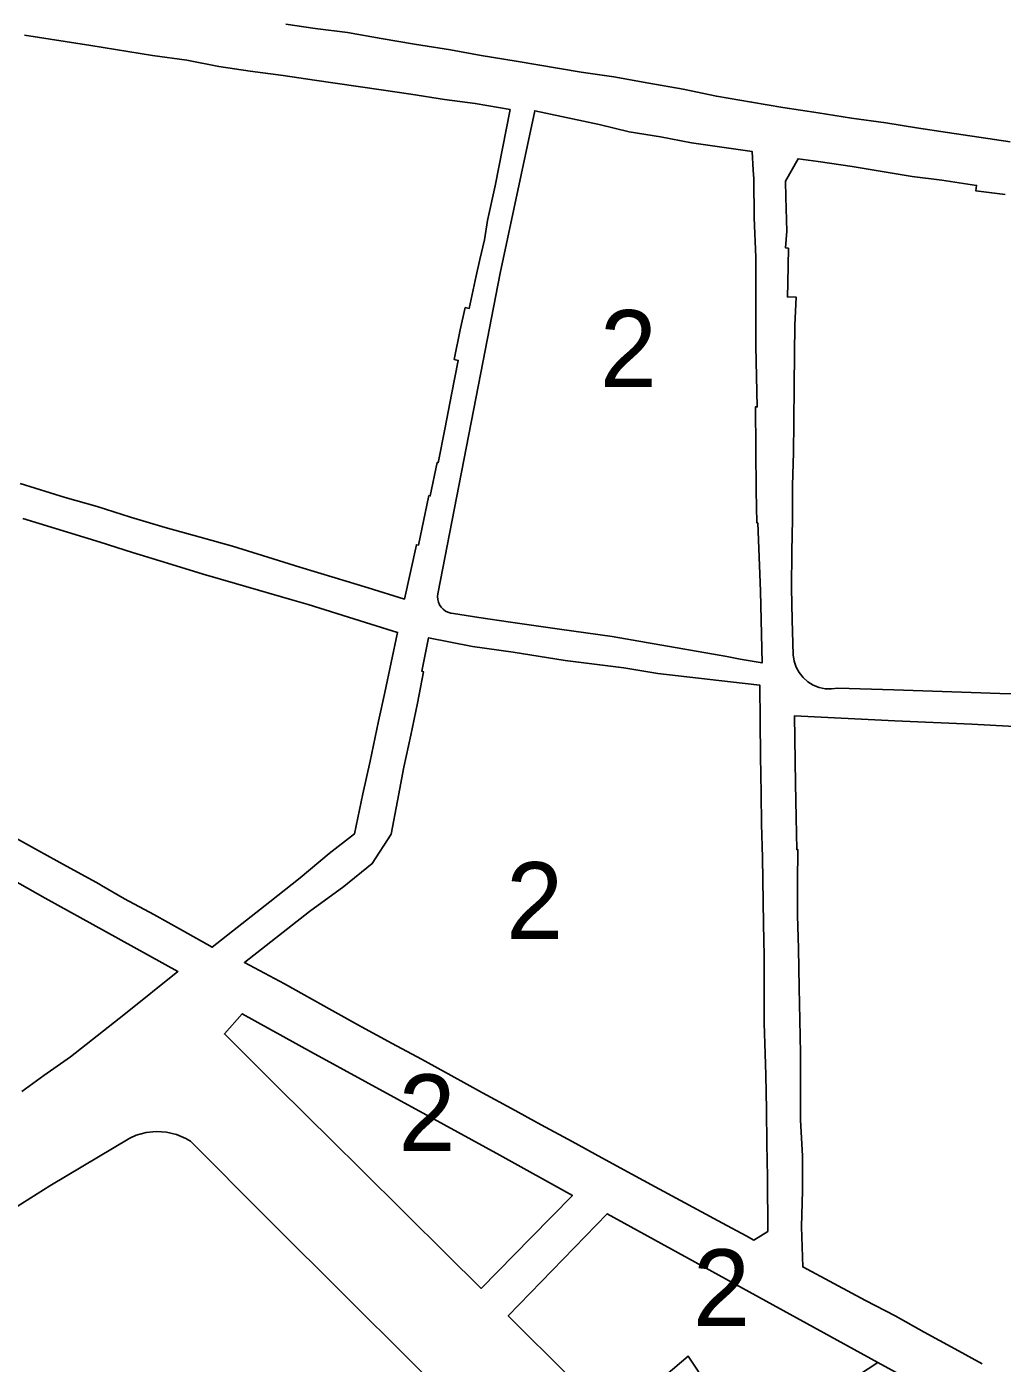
# Model space of a CAD drawing. Extents: x 598968 to 613553, y 4409678 to 4430833.
# Drawn here: x 607715.2 to 607867.8, y 4416080 to 4416289 of the extents above; entities that cross this region are included whole.
import ezdxf

# ---------------------------------------------------------------- set-up
doc = ezdxf.new("R2010")
doc.units = 0
for name, color, linetype in [('1', 7, 'Continuous'), ('SUBZONA 2e. CARRERS DE CASES. amb projecte especial', 7, 'Continuous'), ('ZONA 2. CARRERS DE CASES. Cases de trast', 7, 'Continuous')]:
    doc.layers.add(name, color=color, linetype=linetype)

msp = doc.modelspace()

# ---------------------------------------------------------------- linework, layer by layer
at = {"layer": '1'}
for points in [[(607714.8669, 4416287.693), (607725.2068, 4416286.0432), (607734.8867, 4416284.4934), (607740.2266, 4416283.7635), (607745.2466, 4416282.7836), (607750.1465, 4416282.0336), (607755.2965, 4416281.3537), (607760.1964, 4416280.6438), (607770.6563, 4416279.114), (607775.2663, 4416278.4641), (607780.5362, 4416277.6342), (607785.3561, 4416276.9943), (607790.7961, 4416276.0444), (607788.4661, 4416264.1145), (607787.2962, 4416258.7046), (607786.7862, 4416255.6646), (607786.0962, 4416252.5846), (607785.5205, 4416250.0336), (607784.4063, 4416244.9547), (607783.7863, 4416245.0847), (607783.0063, 4416241.5947), (607782.0763, 4416236.9447), (607782.7063, 4416236.8148), (607781.6473, 4416231.4626), (607780.6464, 4416226.3048), (607779.5464, 4416220.8249), (607779.4164, 4416220.8549), (607778.3186, 4416215.6402), (607778.1064, 4416215.6849), (607776.4765, 4416207.935), (607776.1665, 4416207.995), (607774.2765, 4416199.4851), (607768.5866, 4416201.2349), (607763.4356, 4416202.8436), (607757.9167, 4416204.5047), (607755.4167, 4416205.2746), (607752.9168, 4416206.0446), (607747.3982, 4416207.7807), (607742.3469, 4416209.1644), (607736.8669, 4416210.7143), (607731.4103, 4416212.3258), (607726.197, 4416213.984), (607721.2371, 4416215.4039), (607714.1772, 4416217.5738)], [(607869.0152, 4416270.9859), (607859.2305, 4416272.4599), (607854.3954, 4416273.1656), (607849.5937, 4416273.9605), (607844.1855, 4416274.6854), (607838.9965, 4416275.5066), (607833.4656, 4416276.3852), (607828.5707, 4416277.2173), (607823.0857, 4416278.125), (607817.8758, 4416279.2249), (607812.4858, 4416280.1848), (607807.0359, 4416281.1547), (607801.9459, 4416281.8846), (607791.756, 4416283.6044), (607786.3061, 4416284.4843), (607781.4662, 4416285.3742), (607775.8562, 4416286.284), (607770.6463, 4416287.1439), (607765.3963, 4416288.0738), (607760.3364, 4416288.6937), (607755.7264, 4416289.3937)], [(607871.1255, 4416184.6369), (607867.3855, 4416184.7569), (607862.9156, 4416184.8968), (607850.8107, 4416185.2816), (607842.0558, 4416185.5764), (607841.0791, 4416185.4468), (607840.0947, 4416185.4861), (607839.1314, 4416185.693), (607838.2177, 4416186.0614), (607837.3804, 4416186.5807), (607836.6441, 4416187.2354), (607836.0307, 4416188.0063), (607835.558, 4416188.8707), (607835.2399, 4416189.8031), (607835.0859, 4416190.7762), (607834.9258, 4416196.2262), (607834.8358, 4416201.2061), (607834.8558, 4416206.956), (607834.9658, 4416211.986), (607834.9758, 4416217.2359), (607835.1157, 4416222.4359), (607835.1657, 4416227.0958), (607835.2257, 4416232.8357), (607835.2757, 4416237.7757), (607835.3257, 4416242.3456), (607835.5657, 4416246.7056), (607834.1857, 4416246.7444), (607834.2457, 4416248.8755), (607834.3456, 4416254.3655), (607833.8957, 4416254.3954), (607834.0756, 4416257.0254), (607833.9456, 4416262.3654), (607833.8756, 4416264.8353), (607835.8556, 4416268.3553), (607838.9955, 4416267.9054), (607844.2955, 4416267.1355), (607853.7054, 4416265.5857), (607858.3153, 4416264.9958), (607863.7753, 4416264.1759), (607863.6668, 4416263.3157), (607868.2652, 4416262.736)], [(607714.5844, 4416212.0789), (607726.6937, 4416208.4216), (607731.737, 4416206.7942), (607737.1969, 4416205.1243), (607742.8169, 4416203.3944), (607747.8768, 4416201.9446), (607756.6767, 4416199.3747), (607759.2367, 4416198.6448), (607768.1666, 4416195.855), (607773.2166, 4416194.2751), (607772.2066, 4416189.5701), (607771.1966, 4416184.8652), (607770.2466, 4416180.4252), (607768.8967, 4416174.1353), (607767.7967, 4416169.0453), (607766.4567, 4416162.7753), (607762.4868, 4416159.7353), (607757.9669, 4416155.8953), (607753.2369, 4416152.1552), (607748.097, 4416148.1252), (607744.1871, 4416145.0652), (607739.5871, 4416147.6651), (607735.0872, 4416150.1549), (607730.4972, 4416152.6148), (607726.9201, 4416154.6959), (607726.7214, 4416154.8115), (607726.0972, 4416155.1747), (607721.4073, 4416157.7246), (607716.9073, 4416160.2145), (607712.1974, 4416162.8244)], [(607864.6559, 4416079.9281), (607860.3559, 4416082.268), (607855.576, 4416084.8578), (607851.0145, 4416087.4439), (607846.4195, 4416089.8418), (607841.4361, 4416092.4775), (607836.5762, 4416095.0774), (607836.4061, 4416101.3273), (607836.5561, 4416106.9972), (607836.5261, 4416112.4572), (607836.2161, 4416118.0171), (607836.2061, 4416123.217), (607836.2061, 4416128.497), (607836.126, 4416133.7169), (607836.036, 4416138.7069), (607835.896, 4416144.8768), (607835.776, 4416150.0267), (607835.776, 4416155.1767), (607835.826, 4416160.3166), (607835.636, 4416160.3366), (607835.5559, 4416165.3265), (607835.4554, 4416170.6461), (607835.2759, 4416181.2263), (607851.0057, 4416180.4766), (607863.0156, 4416179.9368), (607878.2854, 4416179.1171)], [(607708.522, 4416158.0906), (607718.0973, 4416152.7546), (607727.5472, 4416147.5148), (607738.8571, 4416141.2851), (607730.6773, 4416134.705), (607726.2273, 4416131.195), (607722.0674, 4416127.945), (607717.8874, 4416124.9849), (607714.4175, 4416122.5149)], [(607698.8973, 4416095.1959), (607716.8354, 4416106.5031), (607718.8375, 4416107.7652), (607731.3173, 4416115.1753), (607732.3273, 4416115.6453), (607733.8773, 4416116.0653), (607735.4673, 4416116.2254), (607736.2673, 4416116.2054), (607737.0672, 4416116.1254), (607738.6272, 4416115.7554), (607740.0972, 4416115.1354), (607740.7972, 4416114.7455), (607752.5934, 4416102.8813), (607765.7365, 4416089.816), (607774.5369, 4416081.0865), (607806.3427, 4416049.5958)], [(607806.3427, 4416049.5958), (607774.5369, 4416081.0865), (607765.7365, 4416089.816), (607752.5934, 4416102.8813), (607740.7972, 4416114.7455), (607740.0972, 4416115.1354), (607738.6272, 4416115.7554), (607737.0672, 4416116.1254), (607736.2673, 4416116.2054), (607735.4673, 4416116.2254), (607733.8773, 4416116.0653), (607732.3273, 4416115.6453), (607731.3173, 4416115.1753), (607718.8375, 4416107.7652), (607716.8354, 4416106.5031), (607698.8973, 4416095.1959)]]:
    msp.add_lwpolyline(points, dxfattribs=at)
for points in [[(607789.2462, 4416250.4547), (607794.676, 4416275.8445), (607804.7459, 4416273.6947), (607809.4259, 4416272.5748), (607814.322, 4416271.7676), (607819.1858, 4416270.845), (607828.6757, 4416269.4652), (607828.8457, 4416266.5552), (607828.9257, 4416265.2152), (607828.9957, 4416259.1153), (607829.2557, 4416252.9454), (607829.2434, 4416239.0518), (607829.4658, 4416229.5357), (607829.1858, 4416229.5557), (607829.2958, 4416216.4258), (607829.3959, 4416211.4259), (607829.5459, 4416211.4059), (607829.9759, 4416200.756), (607830.2259, 4416189.5162), (607826.786, 4416190.1261), (607824.696, 4416190.496), (607812.1261, 4416192.6958), (607806.7662, 4416193.6357), (607798.5363, 4416194.8055), (607790.8464, 4416195.9054), (607785.9064, 4416196.6153), (607781.9664, 4416197.2452), (607781.5222, 4416197.3002), (607781.094, 4416197.4306), (607780.6946, 4416197.6326), (607780.3357, 4416197.9002), (607780.0281, 4416198.2254), (607779.7808, 4416198.5985), (607779.6013, 4416199.0086), (607779.4949, 4416199.4433), (607779.4646, 4416199.8899), (607779.5115, 4416200.3351), (607783.1864, 4416219.325), (607786.2163, 4416234.8948)], [(607784.9486, 4416192.1054), (607791.2964, 4416191.1954), (607799.4092, 4416189.9064), (607808.5962, 4416188.7352), (607813.9276, 4416187.8547), (607825.296, 4416186.5561), (607829.8759, 4416186.0162), (607829.926, 4416180.3913), (607829.976, 4416174.9117), (607830.086, 4416169.0764), (607830.136, 4416164.3165), (607830.266, 4416159.0865), (607830.4461, 4416148.7366), (607830.5561, 4416143.6467), (607830.5461, 4416133.1968), (607830.6861, 4416128.3869), (607830.8161, 4416125.09), (607830.8961, 4416119.617), (607830.9462, 4416114.3071), (607831.0762, 4416109.0771), (607831.1262, 4416100.6172), (607828.9362, 4416099.2672), (607827.7362, 4416099.9172), (607824.0563, 4416101.9071), (607813.5164, 4416107.6068), (607809.8564, 4416109.5867), (607805.1638, 4416112.1301), (607800.5065, 4416114.6965), (607795.6746, 4416117.3096), (607791.0166, 4416119.8263), (607786.4967, 4416122.2862), (607781.6067, 4416124.9761), (607776.9267, 4416127.5459), (607772.3568, 4416129.9958), (607767.5468, 4416132.6357), (607762.9669, 4416135.1556), (607755.5338, 4416139.3228), (607749.247, 4416142.6753), (607759.4569, 4416150.6354), (607764.7868, 4416154.5754), (607769.2467, 4416158.1255), (607772.2167, 4416162.7454), (607773.1767, 4416167.9554), (607774.1766, 4416173.2154), (607775.2566, 4416178.1953), (607776.3166, 4416183.2153), (607777.2565, 4416188.1452), (607777.0165, 4416188.2152), (607778.0465, 4416193.4452)], [(607759.7469, 4416128.6356), (607768.1369, 4416124.0508), (607778.2668, 4416118.5211), (607789.1767, 4416112.5663), (607800.5665, 4416106.2466), (607794.0966, 4416099.6566), (607786.3068, 4416091.6965), (607780.7568, 4416097.1864), (607774.5719, 4416103.3212), (607767.188, 4416110.6176), (607763.1969, 4416114.5659), (607754.357, 4416123.3056), (607746.1271, 4416131.5054), (607748.917, 4416134.6454)], [(607866.7359, 4416070.1182), (607867.1096, 4416066.4683), (607838.2363, 4416047.598), (607836.0751, 4416046.2713), (607835.1768, 4416046.0285), (607834.2515, 4416045.9313), (607833.3224, 4416045.9819), (607832.413, 4416046.1791), (607831.5464, 4416046.5179), (607824.5964, 4416053.4577), (607809.7886, 4416068.2553), (607809.7833, 4416068.2513), (607790.5067, 4416087.4167), (607805.9765, 4416103.3868), (607848.3261, 4416080.1378), (607856.156, 4416075.858)]]:
    msp.add_lwpolyline(points, close=True, dxfattribs=at)
at = {"layer": 'SUBZONA 2e. CARRERS DE CASES. amb projecte especial'}
for points in [[(607821.7464, 4416076.4873), (607818.6564, 4416081.1272), (607815.1757, 4416078.1314)], [(607856.156, 4416075.858), (607848.3261, 4416080.1378), (607835.1774, 4416071.5183)]]:
    msp.add_lwpolyline(points, dxfattribs=at)
at = {"layer": 'ZONA 2. CARRERS DE CASES. Cases de trast'}
for points in [[(607714.1772, 4416217.5738), (607721.2371, 4416215.4039), (607726.197, 4416213.984), (607731.4103, 4416212.3258), (607736.8669, 4416210.7143), (607742.3469, 4416209.1644), (607747.3982, 4416207.7807), (607752.9168, 4416206.0446), (607755.4167, 4416205.2746), (607757.9167, 4416204.5047), (607763.4356, 4416202.8436), (607768.5866, 4416201.2349), (607774.2765, 4416199.4851), (607776.1665, 4416207.995), (607776.4765, 4416207.935), (607778.1064, 4416215.6849), (607778.3186, 4416215.6402), (607779.4164, 4416220.8549), (607779.5464, 4416220.8249), (607780.6464, 4416226.3048), (607781.6473, 4416231.4626), (607782.7063, 4416236.8148), (607782.0763, 4416236.9447), (607783.0063, 4416241.5947), (607783.7863, 4416245.0847), (607784.4063, 4416244.9547), (607785.5205, 4416250.0336), (607786.0962, 4416252.5846), (607786.7862, 4416255.6646), (607787.2962, 4416258.7046), (607788.4661, 4416264.1145), (607790.7961, 4416276.0444), (607785.3561, 4416276.9943), (607780.5362, 4416277.6342), (607775.2663, 4416278.4641), (607770.6563, 4416279.114), (607760.1964, 4416280.6438), (607755.2965, 4416281.3537), (607750.1465, 4416282.0336), (607745.2466, 4416282.7836), (607740.2266, 4416283.7635), (607734.8867, 4416284.4934), (607725.2068, 4416286.0432), (607714.8669, 4416287.693)], [(607755.7264, 4416289.3937), (607760.3364, 4416288.6937), (607765.3963, 4416288.0738), (607770.6463, 4416287.1439), (607775.8562, 4416286.284), (607781.4662, 4416285.3742), (607786.3061, 4416284.4843), (607791.756, 4416283.6044), (607801.9459, 4416281.8846), (607807.0359, 4416281.1547), (607812.4858, 4416280.1848), (607817.8758, 4416279.2249), (607823.0857, 4416278.125), (607828.5707, 4416277.2173), (607833.4656, 4416276.3852), (607838.9965, 4416275.5066), (607844.1855, 4416274.6854), (607849.5937, 4416273.9605), (607854.3954, 4416273.1656), (607859.2305, 4416272.4599), (607869.0152, 4416270.9859)], [(607868.2652, 4416262.736), (607863.6668, 4416263.3157), (607863.7753, 4416264.1759), (607858.3153, 4416264.9958), (607853.7054, 4416265.5857), (607844.2955, 4416267.1355), (607838.9955, 4416267.9054), (607835.8556, 4416268.3553), (607833.8756, 4416264.8353), (607833.9456, 4416262.3654), (607834.0756, 4416257.0254), (607833.8957, 4416254.3954), (607834.3456, 4416254.3655), (607834.2457, 4416248.8755), (607834.1857, 4416246.7444), (607835.5657, 4416246.7056), (607835.3257, 4416242.3456), (607835.2757, 4416237.7757), (607835.2257, 4416232.8357), (607835.1657, 4416227.0958), (607835.1157, 4416222.4359), (607834.9758, 4416217.2359), (607834.9658, 4416211.986), (607834.8558, 4416206.956), (607834.8358, 4416201.2061), (607834.9258, 4416196.2262), (607835.0859, 4416190.7762), (607835.2399, 4416189.8031), (607835.558, 4416188.8707), (607836.0307, 4416188.0063), (607836.6441, 4416187.2354), (607837.3804, 4416186.5807), (607838.2177, 4416186.0614), (607839.1314, 4416185.693), (607840.0947, 4416185.4861), (607841.0791, 4416185.4468), (607842.0558, 4416185.5764), (607850.8107, 4416185.2816), (607862.9156, 4416184.8968), (607867.3855, 4416184.7569), (607871.1255, 4416184.6369)], [(607712.1974, 4416162.8244), (607716.9073, 4416160.2145), (607721.4073, 4416157.7246), (607726.0972, 4416155.1747), (607726.7214, 4416154.8115), (607726.9201, 4416154.6959), (607730.4972, 4416152.6148), (607735.0872, 4416150.1549), (607739.5871, 4416147.6651), (607744.1871, 4416145.0652), (607748.097, 4416148.1252), (607753.2369, 4416152.1552), (607757.9669, 4416155.8953), (607762.4868, 4416159.7353), (607766.4567, 4416162.7753), (607767.7967, 4416169.0453), (607768.8967, 4416174.1353), (607770.2466, 4416180.4252), (607771.1966, 4416184.8652), (607772.2066, 4416189.5701), (607773.2166, 4416194.2751), (607768.1666, 4416195.855), (607759.2367, 4416198.6448), (607756.6767, 4416199.3747), (607747.8768, 4416201.9446), (607742.8169, 4416203.3944), (607737.1969, 4416205.1243), (607731.737, 4416206.7942), (607726.6937, 4416208.4216), (607714.5844, 4416212.0789)], [(607878.2854, 4416179.1171), (607863.0156, 4416179.9368), (607851.0057, 4416180.4766), (607835.2759, 4416181.2263), (607835.4554, 4416170.6461), (607835.5559, 4416165.3265), (607835.636, 4416160.3366), (607835.826, 4416160.3166), (607835.776, 4416155.1767), (607835.776, 4416150.0267), (607835.896, 4416144.8768), (607836.036, 4416138.7069), (607836.126, 4416133.7169), (607836.2061, 4416128.497), (607836.2061, 4416123.217), (607836.2161, 4416118.0171), (607836.5261, 4416112.4572), (607836.5561, 4416106.9972), (607836.4061, 4416101.3273), (607836.5762, 4416095.0774), (607841.4361, 4416092.4775), (607846.4195, 4416089.8418), (607851.0145, 4416087.4439), (607855.576, 4416084.8578), (607860.3559, 4416082.268), (607864.6559, 4416079.9281)], [(607714.4175, 4416122.5149), (607717.8874, 4416124.9849), (607722.0674, 4416127.945), (607726.2273, 4416131.195), (607730.6773, 4416134.705), (607738.8571, 4416141.2851), (607727.5472, 4416147.5148), (607718.0973, 4416152.7546), (607708.522, 4416158.0906)]]:
    msp.add_lwpolyline(points, dxfattribs=at)
for points in [[(607829.2434, 4416239.0518), (607829.2557, 4416252.9454), (607828.9957, 4416259.1153), (607828.9257, 4416265.2152), (607828.8457, 4416266.5552), (607828.6757, 4416269.4652), (607819.1858, 4416270.845), (607814.322, 4416271.7676), (607809.4259, 4416272.5748), (607804.7459, 4416273.6947), (607794.676, 4416275.8445), (607789.2462, 4416250.4547), (607786.2163, 4416234.8948), (607783.1864, 4416219.325), (607779.5115, 4416200.3351), (607779.4646, 4416199.8899), (607779.4949, 4416199.4433), (607779.6013, 4416199.0086), (607779.7808, 4416198.5985), (607780.0281, 4416198.2254), (607780.3357, 4416197.9002), (607780.6946, 4416197.6326), (607781.094, 4416197.4306), (607781.5222, 4416197.3002), (607781.9664, 4416197.2452), (607785.9064, 4416196.6153), (607790.8464, 4416195.9054), (607798.5363, 4416194.8055), (607806.7662, 4416193.6357), (607812.1261, 4416192.6958), (607824.696, 4416190.496), (607826.786, 4416190.1261), (607830.2259, 4416189.5162), (607829.9759, 4416200.756), (607829.5459, 4416211.4059), (607829.3959, 4416211.4259), (607829.2958, 4416216.4258), (607829.1858, 4416229.5557), (607829.4658, 4416229.5357)], [(607831.1262, 4416100.6172), (607831.0762, 4416109.0771), (607830.9462, 4416114.3071), (607830.8961, 4416119.617), (607830.8161, 4416125.09), (607830.6861, 4416128.3869), (607830.5461, 4416133.1968), (607830.5561, 4416143.6467), (607830.4461, 4416148.7366), (607830.266, 4416159.0865), (607830.136, 4416164.3165), (607830.086, 4416169.0764), (607829.976, 4416174.9117), (607829.926, 4416180.3913), (607829.8759, 4416186.0162), (607825.296, 4416186.5561), (607813.9276, 4416187.8547), (607808.5962, 4416188.7352), (607799.4092, 4416189.9064), (607791.2964, 4416191.1954), (607784.9486, 4416192.1054), (607778.0465, 4416193.4452), (607777.0165, 4416188.2152), (607777.2565, 4416188.1452), (607776.3166, 4416183.2153), (607775.2566, 4416178.1953), (607774.1766, 4416173.2154), (607773.1767, 4416167.9554), (607772.2167, 4416162.7454), (607769.2467, 4416158.1255), (607764.7868, 4416154.5754), (607759.4569, 4416150.6354), (607749.247, 4416142.6753), (607755.5338, 4416139.3228), (607762.9669, 4416135.1556), (607767.5468, 4416132.6357), (607772.3568, 4416129.9958), (607776.9267, 4416127.5459), (607781.6067, 4416124.9761), (607786.4967, 4416122.2862), (607791.0166, 4416119.8263), (607795.6746, 4416117.3096), (607800.5065, 4416114.6965), (607805.1638, 4416112.1301), (607809.8564, 4416109.5867), (607813.5164, 4416107.6068), (607824.0563, 4416101.9071), (607827.7362, 4416099.9172), (607828.9362, 4416099.2672)], [(607794.0966, 4416099.6566), (607800.5665, 4416106.2466), (607789.1767, 4416112.5663), (607778.2668, 4416118.5211), (607768.1369, 4416124.0508), (607759.7469, 4416128.6356), (607748.917, 4416134.6454), (607746.1271, 4416131.5054), (607754.357, 4416123.3056), (607763.1969, 4416114.5659), (607767.188, 4416110.6176), (607774.5719, 4416103.3212), (607780.7568, 4416097.1864), (607786.3068, 4416091.6965)], [(607848.3261, 4416080.1378), (607805.9765, 4416103.3868), (607790.5067, 4416087.4167), (607809.7833, 4416068.2513), (607809.7886, 4416068.2553), (607809.7809, 4416068.263), (607817.9764, 4416074.5473), (607815.2265, 4416077.4472), (607814.9965, 4416077.9772), (607815.1757, 4416078.1314), (607818.6564, 4416081.1272), (607821.7464, 4416076.4873), (607826.8064, 4416071.2975), (607829.8663, 4416074.0075), (607832.3263, 4416075.6775), (607835.1774, 4416071.5183)]]:
    msp.add_lwpolyline(points, close=True, dxfattribs=at)

# ---------------------------------------------------------------- texts
for p in [(607804.8452, 4416232.6804), (607790.1866, 4416146.3562), (607773.3468, 4416113.171), (607819.4164, 4416085.8191)]:
    msp.add_text('2', height=12, dxfattribs=at).set_placement(p)

doc.saveas('drawing.dxf')
